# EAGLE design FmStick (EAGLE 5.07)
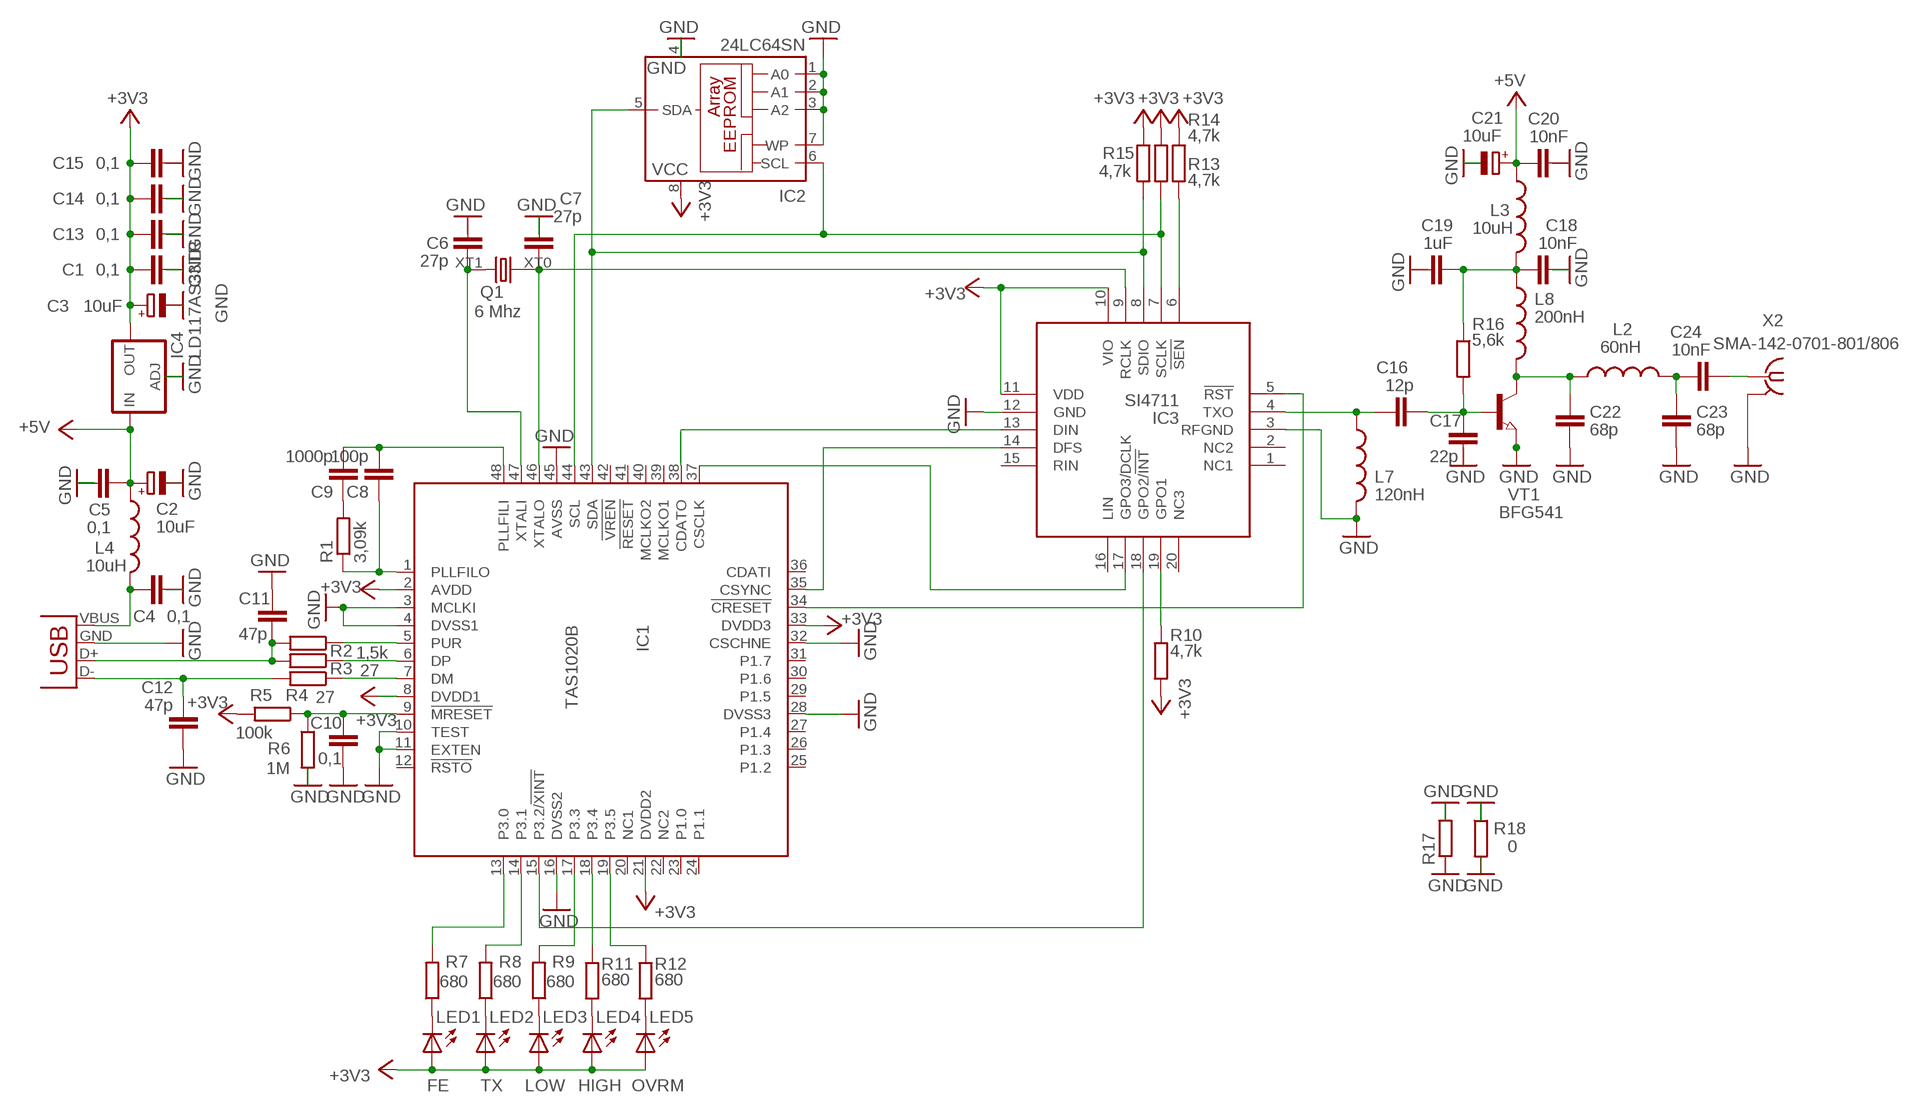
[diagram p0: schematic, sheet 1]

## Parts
C1  0,1  C-EUC0805  [C0805]
C2  10uF  CPOL-EUA/3216-18W  [A/3216-18W]
C3  10uF  CPOL-EUA/3216-18W  [A/3216-18W]
C4  0,1  C-EUC0805  [C0805]
C5  0,1  C-EUC0805  [C0805]
C6  27p  C-EUC0805  [C0805]
C7  27p  C-EUC0805  [C0805]
C8  100p  C-EUC0805  [C0805]
C9  1000p  C-EUC0805  [C0805]
C10  0,1  C-EUC0805  [C0805]
C11  47p  C-EUC0805  [C0805]
C12  47p  C-EUC0805  [C0805]
C13  0,1  C-EUC0805  [C0805]
C14  0,1  C-EUC0805  [C0805]
C15  0,1  C-EUC0805  [C0805]
C16  12p  C-EUC0805  [C0805]
C17  22p  C-EUC0805  [C0805]
C18  10nF  C-EUC0805  [C0805]
C19  1uF  C-EUC0805  [C0805]
C20  10nF  C-EUC0805  [C0805]
C21  10uF  CPOL-EUA/3216-18W  [A/3216-18W]
C22  68p  C-EUC0805  [C0805]
C23  68p  C-EUC0805  [C0805]
C24  10nF  C-EUC0805  [C0805]
IC1  TAS1020B  [PQFP48]
IC2  24LC64SN  [SO-08]
IC3  SI4711  [QFN20]
IC4  LD117AS33TR  [SOT223]
L2  60nH  INDUCTOR1007  [1007]
L3  10uH  INDUCTOR1007  [1007]
L4  10uH  INDUCTOR1007  [1007]
L7  120nH  INDUCTOR1007  [1007]
L8  200nH  INDUCTOR1007  [1007]
LED1  FE  LEDCHIPLED_0805  [CHIPLED_0805]
LED2  TX  LEDCHIPLED_0805  [CHIPLED_0805]
LED3  LOW  LEDCHIPLED_0805  [CHIPLED_0805]
LED4  HIGH  LEDCHIPLED_0805  [CHIPLED_0805]
LED5  OVRM  LEDCHIPLED_0805  [CHIPLED_0805]
Q1  6 Mhz  KX-9A  [KX-9A]
R1  3,09k  R-EU_R0805  [R0805]
R2  1,5k  R-EU_R0805  [R0805]
R3  27  R-EU_R0805  [R0805]
R4  27  R-EU_R0805  [R0805]
R5  100k  R-EU_R0805  [R0805]
R6  1M  R-EU_R0805  [R0805]
R7  680  R-EU_R0805  [R0805]
R8  680  R-EU_R0805  [R0805]
R9  680  R-EU_R0805  [R0805]
R10  4,7k  R-EU_R0805  [R0805]
R11  680  R-EU_R0805  [R0805]
R12  680  R-EU_R0805  [R0805]
R13  4,7k  R-EU_R0805  [R0805]
R14  4,7k  R-EU_R0805  [R0805]
R15  4,7k  R-EU_R0805  [R0805]
R16  5,6k  R-EU_R0805  [R0805]
R17  R-EU_M1206  [M1206]
R18  0  R-EU_R0805  [R0805]
VT1  BFG541  NPN-TRANSISTOR-2EMM  [SOT223]
X2  SMA-142-0701-801/806  [J502-ND-142-0701-801/806]
X3  USB-A-H  [USB-A-H]

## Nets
+3V3: C1.1 C3.+ C13.1 C14.1 C15.1 IC1.2(AVDD) IC1.8(DVDD1) IC1.21(DVDD2) IC1.33(DVDD3) IC2.8(VCC) IC3.10(VIO) IC3.11(VDD) IC4.4(OUT) LED1.A LED2.A LED3.A LED4.A LED5.A R5.2 R10.2 R13.1 R14.1 R15.1
+5V: C2.+ C5.1 C20.1 C21.+ IC4.3(IN) L3.1 L4.1
GND: C1.2 C2.- C3.- C4.2 C5.2 C6.2 C7.2 C10.1 C11.1 C12.1 C13.2 C14.2 C15.2 C17.2 C18.2 C19.1 C20.2 C21.- C22.2 C23.2 IC1.3(MCLKI) IC1.4(DVSS1) IC1.10(TEST) IC1.11(EXTEN) IC1.16(DVSS2) IC1.28(DVSS3) IC1.32(CSCHNE) IC1.45(AVSS) IC2.1(A0) IC2.2(A1) IC2.3(A2) IC2.4(GND) IC2.7(WP) IC3.3(RFGND) IC3.12(GND) IC4.1(ADJ) L7.2 R6.2 R17.1 R17.2 R18.1 R18.2 VT1.1(E) VT1.3(E/) X2.G@1(GND) X3.GND(VBUS)
N$1: C4.1 L4.2 X3.VBUS(GND)
N$2: C8.2 C9.2 IC1.48(PLLFILI)
N$3: C6.1 IC1.47(XTALI) Q1.XT1
N$4: C7.1 IC1.46(XTALO) IC3.9(RCLK) Q1.XT0
N$5: C9.1 R1.2
N$6: C8.1 IC1.1(PLLFILO) R1.1
N$7: IC1.5(PUR) R2.1
N$8: IC1.6(DP) R3.1
N$9: IC1.7(DM) R4.1
N$10: C11.2 R2.2 R3.2 X3.D+(D-)
N$11: C12.2 R4.2 X3.D-(D+)
N$12: IC1.17(P3.3) R9.2
N$13: C10.2 IC1.9(!MRESET) R5.1 R6.1
N$14: IC1.18(P3.4) R11.1
N$15: LED1.C R7.1
N$16: IC1.15(P3.2/!XINT) IC3.18(GPO2/!INT)
N$17: LED2.C R8.1
N$18: LED3.C R9.1
N$19: IC1.13(P3.0) R7.2
N$20: IC1.14(P3.1) R8.2
N$21: LED4.C R11.2
N$22: IC3.19(GPO1) R10.1
N$23: LED5.C R12.2
N$24: IC1.19(P3.5) R12.1
N$25: IC1.43(SDA) IC2.5(SDA) IC3.8(SDIO) R15.2
N$26: IC1.44(SCL) IC2.6(SCL) IC3.7(SCLK) R14.2
N$28: IC1.38(CDATO) IC3.13(DIN)
N$29: IC1.35(CSYNC) IC3.14(DFS)
N$30: IC1.37(CSCLK) IC3.17(GPO3/DCLK)
N$31: IC1.34(!CRESET) IC3.5(!RST)
N$32: IC3.6(!SEN) R13.2
N$33: C16.1 C17.1 R16.2 VT1.2(B)
N$34: C16.2 IC3.4(TXO) L7.1
N$36: C22.1 L2.1 L8.2 VT1.4(C)
N$37: C18.1 C19.2 L3.2 L8.1 R16.1
N$40: C23.1 C24.1 L2.2
N$41: C24.2 X2.1
Unconnected: IC1.12(!RSTO) IC1.20(NC1) IC1.22(NC2) IC1.24(P1.1) IC1.25(P1.2) IC1.27(P1.4) IC1.29(P1.5) IC1.30(P1.6) IC1.31(P1.7) IC1.36(CDATI) IC1.41(!RESET) IC1.42(!VREN) IC3.1(NC1) IC3.2(NC2) IC3.15(RIN) IC3.16(LIN) IC3.20(NC3)

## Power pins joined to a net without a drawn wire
GND: X2.G@2(GND) X2.G@3(GND) X2.G@4(GND)
MCLKO1: IC1.39(MCLKO1)
MCLKO2: IC1.40(MCLKO2)
P1.0: IC1.23(P1.0)
P1.3: IC1.26(P1.3)

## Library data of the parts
C1 C4-C20 C22-C24 = rcl:C-EU: CAPACITOR, European symbol
C2 C3 C21 = rcl:CPOL-EU: POLARIZED CAPACITOR, European symbol
IC1 = tas1020b:TAS1020B: USB Streaming Controller www.ti.com; tas1020b.pdf
IC2 = microchip:24*: Serial EEPROM I2C; MF: MICROCHIP; MPN: 24LC64-I/SN; OC_FARNELL: 9758070; OC_NEWARK: 12C2020
IC3 = si4711:SI4711: FM Stereo transmitter IC SI4711
IC4 = v-reg:LD117A?*: Low drop fixed and adjustable positive voltage regulators 1 A Source: http://www.st.com/stonline/products/literature/ds/7194/ld1117axx.pdf
L2-L4 L7 L8 = SparkFun:INDUCTOR: Inductors
LED1-LED5 = led:LED: LED
Q1 = crystal:KX-9A: CRYSTAL
R1-R18 = rcl:R-EU_: RESISTOR, European symbol
VT1 = bfg541:NPN-TRANSISTOR-2EMM: BFG541
X2 = con-coax:SMA-: SMA 50 Ohm End Launch Jack Receptacle - Round Contact Johnson Components Source: www.johnsoncomponents.com .. J502-ND.pdf; MF: JOHNSON COMPONENTS; MPN: 142-0701-801; OC_FARNELL: 1608592; OC_NEWARK: 90F2624
X3 = SparkFun:USB: USB Connectors USB-B-PTH is fully proven SKU : PRT-00139 USB-miniB is fully proven SKU : PRT-00587 USB-A-PCB is untested. USB-A-H is throughly reviewed, but untested. Spark Fun Electronics SKU : PRT-00437 USB-B-SMT is throughly reviewed, but untested. Needs silkscreen touching up. USB-A-S has not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

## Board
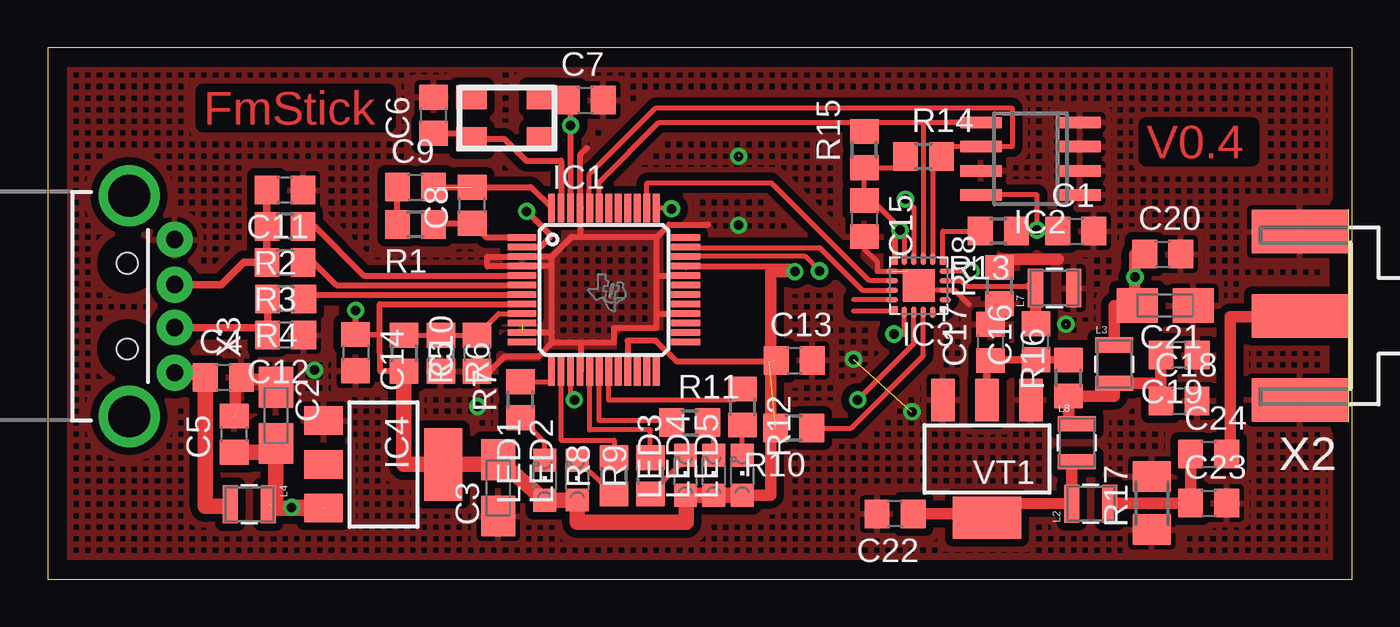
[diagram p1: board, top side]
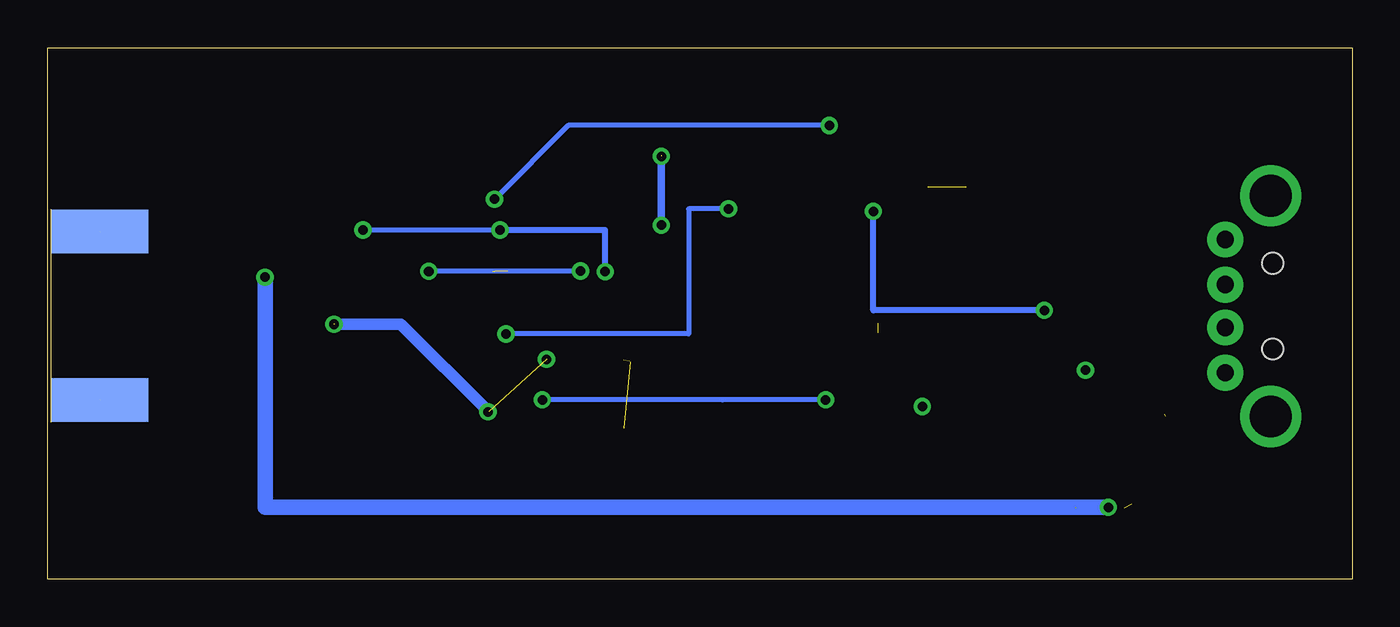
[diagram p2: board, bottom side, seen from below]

Size 68.58 x 27.94 mm. Coordinates in mm from the lower left corner, seen from the top.
Outline: 0,0 68.58,0 68.58,27.94 0,27.94 0,0
Copper layers (1*16): Top 0.035mm / dielectric 1.5mm / Bottom 0.035mm
Design rules "default": minimum track width 10mil, minimum drill 24mil, track to track 8mil, track to pad 8mil, pad to pad 8mil, via to via 8mil, smd to smd 8mil, copper to edge 40mil, drill to drill 8mil, minimum pad ring 10mil, minimum via ring 8mil, stop-mask expansion 4mil, vias tented up to drill 0mil, thermal gap 10mil

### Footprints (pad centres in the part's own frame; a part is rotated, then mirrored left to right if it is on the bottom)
C0805 = smd 1.3 x 1.5: 1 -0.95,0; 2 0.95,0
A/3216-18W = smd 2.15 x 1.8: + 1.475,0; - -1.475,0
PQFP48 = smd 1.5 x 0.35: 1 -4.3,2.75; 2 -4.3,2.25; 3 -4.3,1.75; 4 -4.3,1.25; 5 -4.3,0.75; 6 -4.3,0.25; 7 -4.3,-0.25; 8 -4.3,-0.75; 9 -4.3,-1.25; 10 -4.3,-1.75; 11 -4.3,-2.25; 12 -4.3,-2.75; 25 4.3,-2.75; 26 4.3,-2.25; 27 4.3,-1.75; 28 4.3,-1.25; 29 4.3,-0.75; 30 4.3,-0.25; 31 4.3,0.25; 32 4.3,0.75; 33 4.3,1.25; 34 4.3,1.75; 35 4.3,2.25; 36 4.3,2.75 | smd 0.35 x 1.5: 13 -2.75,-4.3; 14 -2.25,-4.3; 15 -1.75,-4.3; 16 -1.25,-4.3; 17 -0.75,-4.3; 18 -0.25,-4.3; 19 0.25,-4.3; 20 0.75,-4.3; 21 1.25,-4.3; 22 1.75,-4.3; 23 2.25,-4.3; 24 2.75,-4.3; 37 2.75,4.3; 38 2.25,4.3; 39 1.75,4.3; 40 1.25,4.3; 41 0.75,4.3; 42 0.25,4.3; 43 -0.25,4.3; 44 -0.75,4.3; 45 -1.25,4.3; 46 -1.75,4.3; 47 -2.25,4.3; 48 -2.75,4.3
SO-08 = smd 0.6 x 2.2: 1 -1.905,-2.6; 2 -0.635,-2.6; 3 0.635,-2.6; 4 1.905,-2.6; 5 1.905,2.6; 6 0.635,2.6; 7 -0.635,2.6; 8 -1.905,2.6
QFN20 = smd 0.34 x 0.34: 1 -1.265,1.265; 6 -1.265,-1.265; 11 1.265,-1.265; 16 1.265,1.265 | smd 0.61 x 0.28: 2 -1.4,0.75; 3 -1.4,0.25; 4 -1.4,-0.25; 5 -1.4,-0.75; 12 1.4,-0.75; 13 1.4,-0.25; 14 1.4,0.25; 15 1.4,0.75 | smd 0.28 x 0.61: 7 -0.75,-1.4; 8 -0.25,-1.4; 9 0.25,-1.4; 10 0.75,-1.4; 17 0.75,1.4; 18 0.25,1.4; 19 -0.25,1.4; 20 -0.75,1.4 | smd 1.7 x 1.7: GND 0,0
SOT223 = smd 1.5 x 2: 1 -2.3,-3.15; 2 0,-3.15; 3 2.3,-3.15 | smd 3.8 x 2: 4 0,3.15
1007 = smd 2 x 0.8: 1 0,1; 2 0,-1
CHIPLED_0805 = smd 1.2 x 1.2: A 0,-1.05; C 0,1.05
KX-9A = smd 1.6 x 1.25: NC -1.85,1.1; NC@1 1.85,-1.1; XT0 -1.85,-1.1; XT1 1.85,1.1
R0805 = smd 1.3 x 1.5: 1 -0.95,0; 2 0.95,0
M1206 = smd 1.6 x 2: 1 -1.4,0; 2 1.4,0
SOT223' = smd 1.219 x 2.235: 1 -2.311,-3.099; 2 0,-3.099; 3 2.311,-3.099 | smd 3.6 x 2.2: 4 0,3.099
J502-ND-142-0701-801/806 = smd 5.08 x 2.286: 1 2.565,0; G@1 2.565,4.42; G@2 2.565,-4.42 | smd 5.08 x 2.286 bottom: G@3 2.565,4.42; G@4 2.565,-4.42
USB-A-H = drill 0.914 pad 1.88 round: D+ 2.4,1.127; D- 2.4,-1.127; GND 2.4,3.5; VBUS 2.4,-3.5 | drill 2.2 round: GND2 0,-5.8; GND3 0,5.8 | hole 1.1: -0.1,2.25; -0.1,-2.25

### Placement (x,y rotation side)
C1  54.04,18.29 0 top
C2  12,8.6 270 top
C3  23.69,4.79 90 top
C4  9.24,10.6 0 top
C5  9.81,7.62 90 top
C6  20.29,24.38 90 top
C7  28.26,25.18 0 top
C8  22.32,19.65 90 top
C9  19.34,20.61 0 top
C10  22.57,11.87 90 top
C11  12.48,20.45 180 top
C12  12.51,12.83 180 top
C13  39.24,11.49 0 top
C14  16.19,11.91 270 top
C15  42.93,18.95 270 top
C16  51.94,12.48 90 top
C17  49.56,12.45 90 top
C18  59.47,9.37 0 top
C19  59.47,11.78 180 top
C20  58.61,17.08 0 top
C21  58.74,14.38 180 top
C22  44.55,3.43 180 top
C23  61.02,4 0 top
C24  61.02,6.57 0 top
IC1  29.24,15.21 0 top
IC2  51.66,22.1 90 top
IC3  45.78,15.43 180 top
IC4  17.65,6.03 270 top
L2  54.83,3.97 90 top
L3  56.07,11.3 0 top
L4  10.6,3.94 270 top
L7  52.93,15.3 90 top
L8  54.1,7.18 0 top
LED1  26.13,5.21 0 top
LED2  27.84,5.21 0 top
LED3  33.53,5.46 0 top
LED4  35.02,5.46 0 top
LED5  36.51,5.46 0 top
Q1  24.13,24.23 180 top
R1  19.34,18.64 180 top
R2  12.48,18.54 180 top
R3  12.48,16.64 180 top
R4  12.51,14.73 180 top
R5  18.73,11.87 270 top
R6  20.67,11.87 270 top
R7  24.86,9.43 90 top
R8  29.78,5.43 90 top
R9  31.69,5.43 90 top
R10  39.21,7.94 180 top
R11  33.75,8.22 0 top
R12  36.51,9.05 270 top
R13  49.97,18.29 180 top
R14  46.04,22.22 0 top
R15  42.93,22.57 90 top
R16  53.66,10.57 90 top
R17  58.04,4 90 top
R18  50.04,15.43 90 top
VT1  BFG541  [SOT223']  49.37,6.32 180 top
X2  68.39,13.84 180 top
X3  4.29,14.35 0 top

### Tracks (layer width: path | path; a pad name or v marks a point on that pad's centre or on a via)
+3V3  (via drill 0.5)  (2 unrouted)
  Top 0.254: IC3.10 45.03,18.35 44.93,18.35 | 45.03,22.23 R14.1 44.49,21.62 R15.1 C15.1 | C15.1 42.93,19.84 | C15.1 | v44.8,18.35 44.93,18.35 | 52.01,18.29 v52.01,18.35 52.01,20.19 IC2.8 | 52.01,18.29 R13.1 | 52.01,18.29 C1.1 | C1.1 | 44.93,18.35 43.43,19.84 42.99,19.84 C15.1 | LED4.A
  Top 0.305: IC1.8 17.46,14.46 17.46,12.82 | R5.2 17.49,10.92 17.46,12.82 | 17.46,12.82 C14.1 v16.19,14.13 | IC1.21 30.49,12.54 31.97,12.54 33.08,11.43 37.94,11.43 37.94,11.46 | IC1.33 33.54,16.41 39.02,16.41 v39.27,16.16 | IC1.2 25.9,17.46 26.42,17.97 26.42,18.1 v25.18,19.34 | IC3.11 44.52,18.35 v44.8,18.35
  Top 0.61: 38.01,11.46 37.94,11.46 | 38.01,11.46 38.01,4.41 LED5.A | 38.01,11.46 38.01,16.16 v39.27,16.16
  Top 0.813: LED5.A LED4.A LED3.A 33.56,4.41 33.56,2.98 27.84,2.98 LED2.A LED1.A C3.+ 23.69,6.03 IC4.4 18.73,6.03 R5.2
  Bottom 0.254: v44.8,18.35 v52.01,18.35
  Bottom 0.305: v16.19,14.13 25.18,14.13 v25.18,19.34 | v44.8,18.35 39.27,18.35 v39.27,16.16
+5V  (via drill 0.5)  (2 unrouted)
  Top 0.61: C20.1 57.15,17.08 v57.15,15.88 57.15,14.38 C21.+ 56.07,14.38 L3.1
  Top 0.813: v12.83,3.78 14.55,3.78 | C2.+ 12.21,6.93 | C2.+ 11.54,6.67 C5.1 | IC4.3 12,3.73 C2.+
  Bottom 0.813: v12.83,3.78 57.15,3.78 v57.15,15.88
GND  (via drill 0.5)  (9 unrouted)
  Top 0.254: 48.42,14.45 47.69,15.18 IC3.3 46.06,15.18 45.06,16.18 | 43.59,16.19 43.59,16.7 42.93,17.37 C15.2 | 43.59,16.19 43.59,16.18 | 45.56,15.81 45.18,16.19 43.59,16.19
  Top 0.305: 26.51,12.96 IC1.11 | C10.1 23.24,10.93 24.04,11.72 25.81,11.72 26.51,12.41 26.51,12.45 | 26.51,12.45 26.51,12.96 | 26.51,12.45 28.04,12.45 | 28.04,12.45 28.04,10.91 IC1.16 | 28.04,12.45 29.78,12.45 29.78,13.21 32,13.21 32,13.96 | 32,13.96 32,15.96 | 28.04,18 32,18 32,15.96 | 32,13.96 IC1.28 | 32,15.96 IC1.32 | IC1.45 28.04,19.51 28.04,18 | 26.51,16.96 IC1.3 | 26.51,16.46 26.51,16.96 | 26.51,16.46 IC1.4 | 26.51,12.96 26.51,16.46 | 26.51,16.96 27.55,18 28.04,18 | 28,19.88 28,22.32 28.35,22.67 | 32.07,18.03 32.67,18.64 34.7,18.64 | 24.64,16.95 23.11,16.95 23.11,16.45 24.67,16.45
  Top 0.61: 9.87,8.67 9.87,10.51 12,10.51 | 50.04,16.83 53.12,16.83
  Bottom 0.406: 36.26,18.61 v36.32,18.61 36.32,22.29
  Bottom 0.61: 53.5,13.4 50.01,13.4 45.4,8.79
  other vias: 36.32,22.23 22.61,9.08 14.03,10.99 45.43,8.79 42.35,11.56 53.53,13.4
  pour Top (isolate 0.406, hatched): 0,27.94 0,0 68.58,0 68.58,27.94
N$1
  Top 0.813: X3.VBUS 8.04,10.85 C4.1 8.29,3.83 9.61,3.83 L4.2
N$2  (1 unrouted)
  Top 0.305: C9.2 25.39,20.61 IC1.48
N$3
  Top 0.305: 22.02,22.83 Q1.XT1 22.3,23.15 22.8,23.15 | IC1.47 26.99,22 25.15,22 24,23.15 22.8,23.15 | C6.1 22.51,23.43 22.8,23.15
N$4  (via drill 0.5)
  Top 0.254: v27.5,23.84 | 27.5,23.81 v27.5,23.84 | v45.09,19.97 45.53,19.52 IC3.9
  Top 0.305: IC1.46 27.49,22.73 27.5,23.81 v27.5,23.84 27.5,25.18 C7.1 26.02,25.18 25.69,24.85 Q1.XT0
  Bottom 0.254: v27.5,23.84 41.21,23.84 v45.09,19.97
N$5
  Top 0.305: R1.2 C9.1
N$6
  Top 0.305: IC1.1 23.07,17.96 C8.1 20.35,18.7 R1.1
N$7
  Top 0.305: IC1.5 16.62,15.96 14.03,18.54 R2.1
N$8
  Top 0.305: IC1.6 15.18,15.46 14,16.64 R3.1
N$9
  Top 0.254: R4.1 arc-90 13.62,14.96
  Top 0.305: IC1.7 13.69,14.96 R4.1
N$10
  Top 0.406: R3.2 | R3.2 R2.2 C11.2 | X3.D+ 9.13,15.48 10.32,16.67 11.5,16.67 R3.2
N$11
  Top 0.406: R4.2 C12.2 11.16,13.22 X3.D-
N$12
  Top 0.254: R9.2 | R9.2 31.69,7.84 28.49,7.84 IC1.17
N$13
  Top 0.254: IC1.9 23.71,13.96 C10.2 R6.1 R5.1
N$14
  Top 0.254: IC1.18 28.99,8.35 32.8,8.35 R11.1
N$15
  Top 0.254: R7.1 26.13,7.21 LED1.C
N$16  (via drill 0.5)
  Top 0.254: IC3.18 45.53,12.38 42.55,9.4 v42.58,9.43 | v27.69,9.43 27.49,9.43 IC1.15
  Bottom 0.254: v42.58,9.43 33.12,9.43 v27.69,9.43
N$17
  Top 0.254: LED2.C R8.1
N$18
  Top 0.254: R9.1 33.53,6.32 LED3.C
N$19
  Top 0.254: IC1.13 26.49,10.38 R7.2
N$20
  Top 0.254: IC1.14 26.99,7.3 29.78,7.3 R8.2
N$21
  Top 0.254: R11.2 35.02,8.22 LED4.C
N$22
  Top 0.254: IC3.19 46.03,11.74 42.23,7.94 R10.1
N$23
  Top 0.254: R12.2 | LED5.C R12.2
N$24
  Top 0.254: IC1.19 29.49,9.43 35.94,9.43 arc90 R12.1
N$25
  Top 0.254: 47.4,24 IC2.5 46.03,24 | IC1.43 28.99,20.86 32.13,24 43.05,24 46.03,24 | 46.03,24 IC3.8
  Top 0.305: R15.2 42.93,23.88 43.05,24
N$26
  Top 0.254: IC3.7 46.53,22.73 46.99,22.73 | 46.99,22.73 R14.2 | 46.99,22.73 IC2.6 50.7,22.73 50.7,24.73 50.67,24.77 31.97,24.77 28.48,21.27 IC1.44
N$28
  Top 0.254: IC1.38 31.5,20.8 31.53,20.83 38.04,20.83 43.15,15.72 44.35,15.72 IC3.13
N$29
  Top 0.254: IC1.35 33.57,17.43 40.58,17.43 42.83,15.18 IC3.14
N$30  (via drill 0.5)
  Top 0.254: IC3.17 45.02,14.02 45.02,12.89 | 45.02,12.89 45.02,12.86 | v32.8,19.46 32.75,19.51 IC1.37 | v44.48,12.89 45.02,12.89
  Bottom 0.254: v32.8,19.46 34.89,19.46 34.89,12.89 v44.48,12.89
N$31  (via drill 0.5)
  Top 0.254: IC1.34 33.57,16.99 39.78,16.99 v40.58,16.19 | v48.55,16.18 IC3.5
  Bottom 0.254: v48.55,16.18 v40.59,16.18 v40.58,16.19
N$32
  Top 0.254: IC3.6 47.05,18.29 R13.2
N$33
  Top 0.406: R16.2 51.5,11.52 C16.1 49.56,11.53 C17.1 49.37,11.5 VT1.2
N$34
  Top 0.254: IC3.4 48.01,15.68 48.32,15.4 51.55,15.4
  Top 0.406: 51.55,15.4 51.91,15.4 C16.2
  Top 0.61: L7.1 51.94,15.3 C16.2
N$35
  Top 0.254: 42.35,14.7 44.51,14.7
N$36
  Top 0.61: 54.2,6.23 L8.2 53.83,6.21 L2.1 50.15,4 VT1.4 49.37,3.43 C22.1
N$37
  Top 0.406: 58.65,9.16 C18.1 58.68,9.21
  Top 0.61: L8.1 53.66,8.21 R16.1 56.07,9.62 L3.2 58.52,10.3 C18.1 | C18.1 | C18.1 C19.2
N$38
  Top 0.254: 42.35,14.1 44.48,14.1
N$40
  Top 0.61: L2.2 55.83,4 C23.1 C24.1
N$41
  Top 0.61: X2.1 66.9,13.78 62.17,13.78 62.17,6.22 C24.2

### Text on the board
Top: FmStick | V0.4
